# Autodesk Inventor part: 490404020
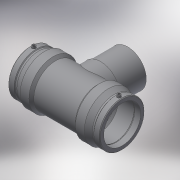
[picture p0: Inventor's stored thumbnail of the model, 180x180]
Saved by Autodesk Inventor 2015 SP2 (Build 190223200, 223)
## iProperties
Created: 2017-06
Part Number: 490404020
Material: Generic
Description: PLASSON TEE 20-20-20
Document SubType Name: Modeling
Designer: KIM
Mass: 62.3851 g
Surface Area: 246.236 cm^2
Volume: 62.3851 cm^3
Density: 1 g/cm^3
Appearance: Default
Author: KIM
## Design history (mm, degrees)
derived "490404.ipt"
feature "Solid1::490404.ipt"
tag "TaggingFeature1"
body "Solid1"
other parameters: "d0" = 96, "d2" = 33, "d3" = 37, "d4" = 24, "d5" = 29.7, "d6" = 19, "d8" = 168 deg, "d10" = 14.8, "d11" = 4.93333, "d13" = 96, "d14" = 17.6296, "d17" = 18, "d19" = 3.52592, "d20" = 168 deg, "d22" = 30.69, "d23" = 33, "d24" = 29.7693, "d25" = 135 deg, "d26" = 67.2, "d27" = 135 deg, "d29" = 39, "d30" = 15, "d31" = 38.4, "d34" = 5 deg, "d35" = 15, "d39" = 5 deg, "d40" = 9.6, "d41" = 4.8, "d42" = 6, "d43" = 0, "d45" = 4, "d46" = 14, "d47" = 0, "d51" = 0, "d52" = 16, "d54" = 0, "d55" = 29.7, "d56" = 33, "d57" = 33.6, "d58" = 135 deg, "d59" = 37, "d60" = 37, "d61" = 135 deg, "d72" = 43.68, "d73" = 21.84, "d75" = 21, "d77" = 0, "d78" = 16, "d80" = 0, "d82" = 43.5, "d83" = 0, "d84" = 3, "d85" = 0, "d86" = 3, "d87" = 0, "d88" = 10.73, "d89" = 2.6825, "d90" = 10.73, "L_" = 96, "L_1" = 37, "D_" = 33, "A_" = 39, "d_2" = 12
